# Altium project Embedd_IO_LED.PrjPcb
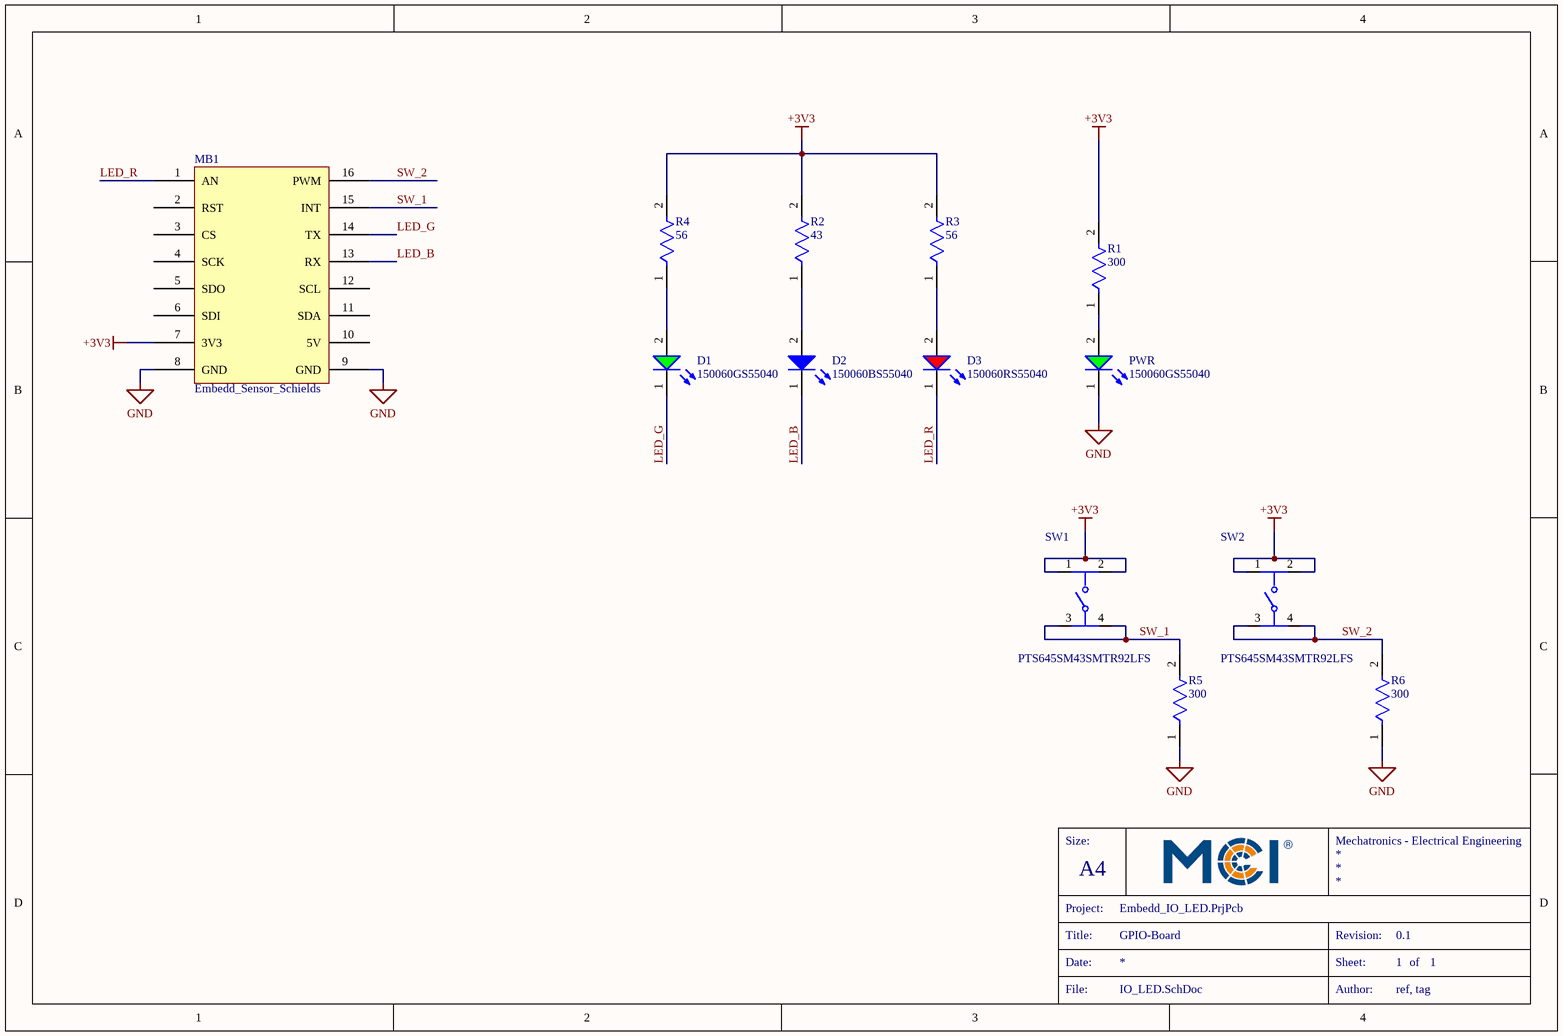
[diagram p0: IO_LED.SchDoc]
1 sheet, 13 parts. Net scope: global (net labels, ports and power ports of the same name join across sheets).
Board files: IO_PCB_LED.PcbDoc, IO_PCB_LED_Array.PcbDoc

## Sheet IO_LED.SchDoc: GPIO-Board
size A4; Author: ref, tag; Revision: 0.1; SheetNumber: 1; SheetTotal: 1

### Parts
D1  150060GS55040  [WL-SMCD_0603]
D2  150060BS55040  [WL-SMCD_0603]
D3  150060RS55040  [WL-SMCD_0603]
MB1  Embedd_Sensor_Schields  [Embedd_add_on_board_25,4 x 22,86]
PWR  150060GS55040  [WL-SMCD_0603]
R1  300  [FP-CRCW0603-HPe3-IPC_C]
R2  43  [FP-CRCW0603-e3-IPC_A]
R3  56  [FP-CRCW0603-e3-IPC_A]
R4  56  [FP-CRCW0603-e3-IPC_A]
R5  300  [FP-CRCW0603-e3-IPC_A]
R6  300  [FP-CRCW0603-e3-IPC_A]
SW1  PTS645SM43SMTR92LFS  [FP-PTS645SM43SMTR92LFS-MFG]
SW2  PTS645SM43SMTR92LFS  [FP-PTS645SM43SMTR92LFS-MFG]

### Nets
+3V3: MB1.7(3V3) R1.2 R2.2 R3.2 R4.2 SW1.1 SW1.2 SW2.1 SW2.2
GND: MB1.8(GND) MB1.9(GND) PWR.1(K) R5.1 R6.1
LED_B: D2.1(K) MB1.13(RX)
LED_G: D1.1(K) MB1.14(TX)
LED_R: D3.1(K) MB1.1(AN)
SW_1: MB1.15(INT) R5.2 SW1.3 SW1.4
SW_2: MB1.16(PWM) R6.2 SW2.3 SW2.4
NetD1_2: D1.2(A) R4.1
NetD2_2: D2.2(A) R2.1
NetD3_2: D3.2(A) R3.1
NetPWR_2: PWR.2(A) R1.1

Not connected (* = marked no-connect by the designer): MB1 2(RST) 3(CS) 4(SCK) 5(SDO) 6(SDI) 10(5V) 11(SDA) 12(SCL)

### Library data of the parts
D1 PWR = CMP-03913-90235563-2: 150060GS55040 WL-SMCD SMT Mono-color Chip LED Diffused; Forward Voltage: 3.2V; Forward Current: 60mA; Luminous Intensity: 430mcd; Peak Wavelength: 520nm; Viewing Angle: 140°; Wavelength: 525nm; Max Reverse Voltage (DC): 5V
D2 = CMP-03913-90235561-2: 150060BS55040 WL-SMCD SMT Mono-color Chip LED Diffused; Dominant Wavelength: 470nm; Forward Current: 60mA; Viewing Angle: 140°; Peak Wavelength: 465nm; Max Reverse Voltage (DC): 5V; Forward Voltage: 3.2V; Luminous Intensity: 80mcd
D3 = CMP-207942-000007-3: LED RED DIFFUSED 0603 SMD; NexarPartId: 90235565; Reverse Voltage: 5V; Power Dissipation: 48mW; Luminous Intensity: 90mcd; Forward Voltage: 2V; Wavelength: 624nm; Max Junction Temperature (Tj): 115°C; Peak Wavelength: 632nm; Forward Current: 40mA; Viewing Angle: 140°
MB1 = CMP-00030-00005-3: Footprint for sensor shields
R1 = CMP-02407-005270-1: RES Thick Film, 300Ω, 1%, 0.33W, 100ppm/°C, 0603; Resistance: 300R; Voltage Rating: 75V; Power Rating: 250mW
R2-R6 = CMP-2000-03250-2: RES Thick Film, 33Ω, 1%, 0.1W, 100ppm/°C, 0603; Voltage Rating: 75V; Max Power Dissipation: 100mW; Resistance: 33R
SW1 SW2 = CMP-2000-05160-2: SWITCH TACTILE SPST-NO 0.05A 12V; Contact Resistance: 100mR; Throw Configuration: SPST; Illumination Type: Non-Illuminated; Mechanical Life: 100000Cycles; Current Rating: 50mA; Switch Function: Off-Mom; Actuator Length: 0.85mm; Actuator Material: Nylon; Actuator Type: Standard; Operating Force: 160gf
